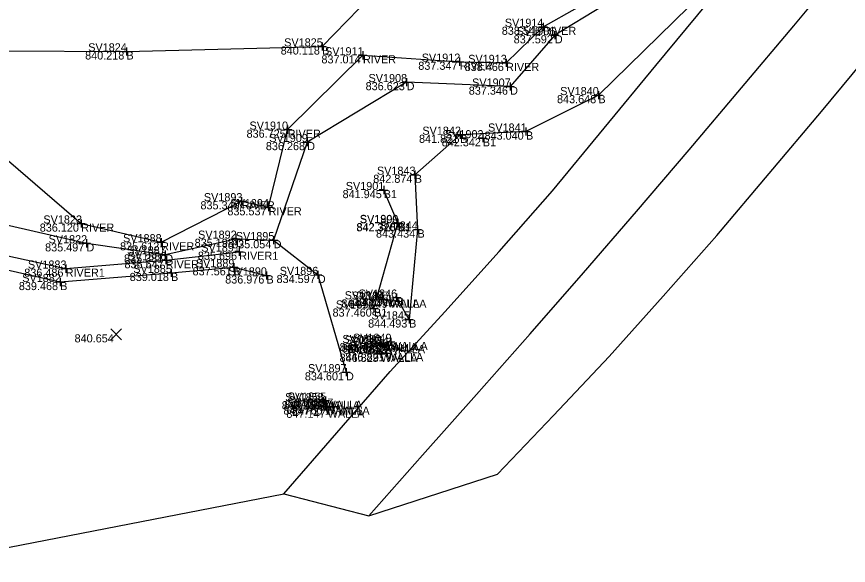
# Model space of a CAD drawing. Extents: x 2125299 to 2129212, y 713100 to 714300.
# Drawn here: x 2127803.8 to 2127906.4, y 713553 to 713620.7 of the extents above; entities that cross this region are included whole.
import ezdxf

# ---------------------------------------------------------------- set-up
doc = ezdxf.new("R2010")
doc.units = 0
for name, color, linetype in [('DR_X_Ditch', 7, 'Continuous'), ('DT_X_Terrain_Boundary', 7, 'Continuous'), ('HY_X_Water_Edge', 7, 'Continuous'), ('PM_X_CL_Double_Solid', 7, 'Continuous'), ('PV_X_EOP', 7, 'Continuous'), ('RW_P_Esmt_TMP', 7, 'Continuous'), ('RW_X_CL_100_Curve_Data', 7, 'Continuous'), ('RW_X_Esmt_CH', 7, 'Continuous'), ('RW_X_Fee_WL', 7, 'Continuous'), ('SV_X_Break_Lines', 7, 'Continuous'), ('SV_X_Mon_Cells_Found', 7, 'Continuous'), ('SV_X_Text_Elevation', 7, 'Continuous')]:
    doc.layers.add(name, color=color, linetype=linetype)

msp = doc.modelspace()

# ---------------------------------------------------------------- linework, layer by layer
at = {"layer": 'DR_X_Ditch'}
for points in [[(2127754.53, 713650.69), (2127755.51, 713649.81), (2127761.02, 713641.8), (2127767.38, 713629.63), (2127773.83, 713613.84), (2127787.1, 713602.06), (2127796.41, 713596.43), (2127812.41, 713592.76), (2127822.14, 713591.39), (2127830.86, 713593.33), (2127835.51, 713593.15), (2127840.96, 713588.86), (2127844.44, 713576.86)], [(2127902.43, 713649.34), (2127886.72, 713632.53), (2127876.19, 713622.06), (2127870.21, 713618.42), (2127864.69, 713612.09), (2127851.92, 713612.64), (2127839.65, 713605.25), (2127835.51, 713593.15)]]:
    msp.add_lwpolyline(points, dxfattribs=at)
at = {"layer": 'DT_X_Terrain_Boundary'}
msp.add_lwpolyline([(2127597.81, 713640.57), (2127738.64, 713599.23), (2127748.23, 713588.26), (2127764.66, 713569.48), (2127770.03, 713566.16), (2127791.25, 713553.04), (2127836.75, 713561.85), (2127847.25, 713559.16), (2127863.15, 713564.3), (2127870.03, 713571.54), (2127876.91, 713578.79), (2127883.56, 713586.26), (2127890.21, 713593.73), (2127896.66, 713601.37), (2127903.1, 713609.02), (2127909.49, 713616.71)], dxfattribs=at)
at = {"layer": 'HY_X_Water_Edge'}
for points in [[(2127760.76, 713650.39), (2127768.15, 713637.25), (2127774.73, 713633.04), (2127778.54, 713623.49), (2127790.38, 713611.58), (2127799.45, 713605.77), (2127811.76, 713595.2), (2127821.63, 713592.89), (2127831.56, 713597.95), (2127834.89, 713597.21), (2127837.24, 713606.78), (2127846.53, 713615.95), (2127858.46, 713615.16), (2127864.19, 713615.01), (2127868.76, 713619.47), (2127877.26, 713624.25)], [(2127759.04, 713637.44), (2127761.13, 713628.45), (2127763.15, 713621.24), (2127764.16, 713612.4), (2127775.86, 713605.03), (2127792.88, 713593.37), (2127809.85, 713589.64), (2127822.2, 713590.68), (2127831.26, 713591.73)]]:
    msp.add_lwpolyline(points, dxfattribs=at)
at = {"layer": 'PM_X_CL_Double_Solid'}
msp.add_lwpolyline([(2127847.25, 713559.16), (2127853.89, 713566.63), (2127860.53, 713574.11), (2127867.15, 713581.61), (2127873.74, 713589.13), (2127880.29, 713596.69), (2127886.77, 713604.3), (2127893.23, 713611.93), (2127899.68, 713619.58), (2127906.08, 713627.26), (2127912.37, 713635.04)], dxfattribs=at)
at = {"layer": 'PV_X_EOP'}
for points in [[(2127836.75, 713561.85), (2127843.31, 713569.4), (2127849.87, 713576.94), (2127856.63, 713584.32), (2127863.34, 713591.74), (2127869.93, 713599.25), (2127876.3, 713606.96), (2127882.68, 713614.67), (2127889.03, 713622.38), (2127895.18, 713630.27), (2127901.47, 713638.05), (2127907.73, 713645.84)], [(2127863.15, 713564.3), (2127870.03, 713571.54), (2127876.91, 713578.79), (2127883.56, 713586.26), (2127890.21, 713593.73), (2127896.66, 713601.37), (2127903.1, 713609.02), (2127909.49, 713616.71)]]:
    msp.add_lwpolyline(points, dxfattribs=at)
at = {"layer": 'SV_X_Break_Lines'}
for points in [[(2127802.01, 713616.51), (2127817.35, 713616.43), (2127841.48, 713617.04), (2127847.58, 713623.34), (2127853.96, 713625.47), (2127861.44, 713624.91), (2127870.57, 713626.11), (2127879.02, 713631.05), (2127890.36, 713639.22), (2127900.49, 713650.27), (2127902.76, 713651.63), (2127904.08, 713651.05), (2127905, 713647.96), (2127904.71, 713645.4), (2127899.81, 713638.31), (2127886.77, 713621.96), (2127875.58, 713611.04), (2127866.65, 713606.54), (2127858.53, 713606.15), (2127852.92, 713601.22), (2127853.26, 713594.46), (2127852.23, 713583.37), (2127850.69, 713586.06)], [(2127735.75, 713636.66), (2127746.04, 713632.28), (2127758.51, 713628.18), (2127762.63, 713621.24), (2127762.07, 713611.19), (2127774.9, 713604.1), (2127791.54, 713592), (2127809.17, 713587.99), (2127822.85, 713589.11), (2127830.59, 713589.8), (2127834.63, 713588.8)], [(2127847.89, 713584.72), (2127850.83, 713595.23), (2127850.85, 713595.27), (2127849.09, 713599.33)]]:
    msp.add_lwpolyline(points, dxfattribs=at)
at = {"layer": 'SV_X_Mon_Cells_Found'}
for p, q in [((2127868.76, 713619.97), (2127868.76, 713618.97)), ((2127868.26, 713619.47), (2127869.26, 713619.47)), ((2127868.76, 713619.47), (2127868.76, 713619.47)), ((2127870.21, 713618.92), (2127870.21, 713617.92)), ((2127869.71, 713618.42), (2127870.71, 713618.42)), ((2127870.21, 713618.42), (2127870.21, 713618.42)), ((2127817.35, 713616.93), (2127817.35, 713615.93)), ((2127840.98, 713617.04), (2127841.98, 713617.04)), ((2127841.48, 713617.54), (2127841.48, 713616.54)), ((2127841.48, 713617.04), (2127841.48, 713617.04)), ((2127816.85, 713616.43), (2127817.85, 713616.43)), ((2127817.35, 713616.43), (2127817.35, 713616.43)), ((2127846.03, 713615.95), (2127847.03, 713615.95)), ((2127846.53, 713616.45), (2127846.53, 713615.45)), ((2127846.53, 713615.95), (2127846.53, 713615.95)), ((2127858.46, 713615.66), (2127858.46, 713614.66)), ((2127857.96, 713615.16), (2127858.96, 713615.16)), ((2127858.46, 713615.16), (2127858.46, 713615.16)), ((2127863.69, 713615.01), (2127864.69, 713615.01)), ((2127864.19, 713615.51), (2127864.19, 713614.51)), ((2127864.19, 713615.01), (2127864.19, 713615.01)), ((2127851.42, 713612.64), (2127852.42, 713612.64)), ((2127851.92, 713613.14), (2127851.92, 713612.14)), ((2127851.92, 713612.64), (2127851.92, 713612.64)), ((2127864.69, 713612.59), (2127864.69, 713611.59)), ((2127864.19, 713612.09), (2127865.19, 713612.09)), ((2127864.69, 713612.09), (2127864.69, 713612.09)), ((2127875.58, 713611.54), (2127875.58, 713610.54)), ((2127875.08, 713611.04), (2127876.08, 713611.04)), ((2127875.58, 713611.04), (2127875.58, 713611.04)), ((2127836.74, 713606.78), (2127837.74, 713606.78)), ((2127837.24, 713607.28), (2127837.24, 713606.28)), ((2127837.24, 713606.78), (2127837.24, 713606.78)), ((2127858.53, 713606.65), (2127858.53, 713605.65)), ((2127866.15, 713606.54), (2127867.15, 713606.54)), ((2127866.65, 713607.04), (2127866.65, 713606.04)), ((2127866.65, 713606.54), (2127866.65, 713606.54)), ((2127839.65, 713605.75), (2127839.65, 713604.75)), ((2127858.03, 713606.15), (2127859.03, 713606.15)), ((2127858.53, 713606.15), (2127858.53, 713606.15)), ((2127860.82, 713605.72), (2127861.82, 713605.72)), ((2127861.32, 713606.22), (2127861.32, 713605.22)), ((2127861.32, 713605.72), (2127861.32, 713605.72)), ((2127839.15, 713605.25), (2127840.15, 713605.25)), ((2127839.65, 713605.25), (2127839.65, 713605.25)), ((2127852.92, 713601.72), (2127852.92, 713600.72)), ((2127852.42, 713601.22), (2127853.42, 713601.22)), ((2127852.92, 713601.22), (2127852.92, 713601.22)), ((2127848.59, 713599.33), (2127849.59, 713599.33)), ((2127849.09, 713599.83), (2127849.09, 713598.83)), ((2127849.09, 713599.33), (2127849.09, 713599.33)), ((2127831.56, 713598.45), (2127831.56, 713597.45)), ((2127831.06, 713597.95), (2127832.06, 713597.95)), ((2127831.56, 713597.95), (2127831.56, 713597.95)), ((2127834.39, 713597.21), (2127835.39, 713597.21)), ((2127834.89, 713597.71), (2127834.89, 713596.71)), ((2127834.89, 713597.21), (2127834.89, 713597.21)), ((2127811.26, 713595.2), (2127812.26, 713595.2)), ((2127811.76, 713595.7), (2127811.76, 713594.7)), ((2127811.76, 713595.2), (2127811.76, 713595.2)), ((2127850.33, 713595.23), (2127851.33, 713595.23)), ((2127850.35, 713595.27), (2127851.35, 713595.27)), ((2127850.83, 713595.73), (2127850.83, 713594.73)), ((2127850.83, 713595.23), (2127850.83, 713595.23)), ((2127850.85, 713595.77), (2127850.85, 713594.77)), ((2127850.85, 713595.27), (2127850.85, 713595.27)), ((2127852.76, 713594.46), (2127853.76, 713594.46)), ((2127853.26, 713594.96), (2127853.26, 713593.96)), ((2127853.26, 713594.46), (2127853.26, 713594.46)), ((2127812.41, 713593.26), (2127812.41, 713592.26)), ((2127821.63, 713593.39), (2127821.63, 713592.39)), ((2127830.36, 713593.33), (2127831.36, 713593.33)), ((2127830.86, 713593.83), (2127830.86, 713592.83)), ((2127830.86, 713593.33), (2127830.86, 713593.33)), ((2127835.01, 713593.15), (2127836.01, 713593.15)), ((2127835.51, 713593.65), (2127835.51, 713592.65)), ((2127835.51, 713593.15), (2127835.51, 713593.15)), ((2127811.91, 713592.76), (2127812.91, 713592.76)), ((2127812.41, 713592.76), (2127812.41, 713592.76)), ((2127821.13, 713592.89), (2127822.13, 713592.89)), ((2127821.63, 713592.89), (2127821.63, 713592.89)), ((2127831.26, 713592.23), (2127831.26, 713591.23)), ((2127821.64, 713591.39), (2127822.64, 713591.39)), ((2127822.14, 713591.89), (2127822.14, 713590.89)), ((2127822.14, 713591.39), (2127822.14, 713591.39)), ((2127822.2, 713591.18), (2127822.2, 713590.18)), ((2127830.76, 713591.73), (2127831.76, 713591.73)), ((2127831.26, 713591.73), (2127831.26, 713591.73)), ((2127809.85, 713590.14), (2127809.85, 713589.14)), ((2127821.7, 713590.68), (2127822.7, 713590.68)), ((2127822.2, 713590.68), (2127822.2, 713590.68)), ((2127830.59, 713590.3), (2127830.59, 713589.3)), ((2127809.35, 713589.64), (2127810.35, 713589.64)), ((2127809.85, 713589.64), (2127809.85, 713589.64)), ((2127822.35, 713589.11), (2127823.35, 713589.11)), ((2127822.85, 713589.61), (2127822.85, 713588.61)), ((2127822.85, 713589.11), (2127822.85, 713589.11)), ((2127830.09, 713589.8), (2127831.09, 713589.8)), ((2127830.59, 713589.8), (2127830.59, 713589.8)), ((2127834.63, 713589.3), (2127834.63, 713588.3)), ((2127840.96, 713589.36), (2127840.96, 713588.36)), ((2127808.67, 713587.99), (2127809.67, 713587.99)), ((2127809.17, 713588.49), (2127809.17, 713587.49)), ((2127809.17, 713587.99), (2127809.17, 713587.99)), ((2127834.13, 713588.8), (2127835.13, 713588.8)), ((2127834.63, 713588.8), (2127834.63, 713588.8)), ((2127840.46, 713588.86), (2127841.46, 713588.86)), ((2127840.96, 713588.86), (2127840.96, 713588.86)), ((2127848.48, 713585.85), (2127849.48, 713585.85)), ((2127848.98, 713586.35), (2127848.98, 713585.35)), ((2127848.98, 713585.85), (2127848.98, 713585.85)), ((2127849.83, 713586.31), (2127849.83, 713585.31)), ((2127850.19, 713586.06), (2127851.19, 713586.06)), ((2127850.69, 713586.56), (2127850.69, 713585.56)), ((2127850.69, 713586.06), (2127850.69, 713586.06)), ((2127847.89, 713585.22), (2127847.89, 713584.22)), ((2127849.33, 713585.81), (2127850.33, 713585.81)), ((2127849.83, 713585.81), (2127849.83, 713585.81)), ((2127847.39, 713584.72), (2127848.39, 713584.72)), ((2127847.89, 713584.72), (2127847.89, 713584.72)), ((2127852.23, 713583.87), (2127852.23, 713582.87)), ((2127851.73, 713583.37), (2127852.73, 713583.37)), ((2127852.23, 713583.37), (2127852.23, 713583.37)), ((2127848.72, 713580.96), (2127848.72, 713579.96)), ((2127848.97, 713580.84), (2127848.97, 713579.84)), ((2127849.66, 713580.71), (2127849.66, 713579.71)), ((2127849.98, 713581.11), (2127849.98, 713580.11)), ((2127848.22, 713580.46), (2127849.22, 713580.46)), ((2127848.47, 713580.34), (2127849.47, 713580.34)), ((2127848.72, 713580.46), (2127848.72, 713580.46)), ((2127848.97, 713580.34), (2127848.97, 713580.34)), ((2127849.16, 713580.21), (2127850.16, 713580.21)), ((2127849.44, 713579.72), (2127849.44, 713578.72)), ((2127849.48, 713580.61), (2127850.48, 713580.61)), ((2127849.66, 713580.21), (2127849.66, 713580.21)), ((2127849.98, 713580.61), (2127849.98, 713580.61)), ((2127848.24, 713579.14), (2127849.24, 713579.14)), ((2127848.74, 713579.64), (2127848.74, 713578.64)), ((2127848.74, 713579.14), (2127848.74, 713579.14)), ((2127848.94, 713579.22), (2127849.94, 713579.22)), ((2127849.44, 713579.22), (2127849.44, 713579.22)), ((2127843.94, 713576.86), (2127844.94, 713576.86)), ((2127844.44, 713577.36), (2127844.44, 713576.36)), ((2127844.44, 713576.86), (2127844.44, 713576.86)), ((2127841.63, 713573.79), (2127841.63, 713572.79)), ((2127841.91, 713573.86), (2127841.91, 713572.86)), ((2127841.13, 713573.29), (2127842.13, 713573.29)), ((2127841.33, 713572.65), (2127842.33, 713572.65)), ((2127841.41, 713573.36), (2127842.41, 713573.36)), ((2127841.63, 713573.29), (2127841.63, 713573.29)), ((2127841.83, 713573.15), (2127841.83, 713572.15)), ((2127841.83, 713572.65), (2127841.83, 713572.65)), ((2127841.91, 713573.36), (2127841.91, 713573.36)), ((2127842.18, 713572.74), (2127842.18, 713571.74)), ((2127842.32, 713572.62), (2127843.32, 713572.62)), ((2127842.82, 713573.12), (2127842.82, 713572.12)), ((2127842.82, 713572.62), (2127842.82, 713572.62)), ((2127841.68, 713572.24), (2127842.68, 713572.24)), ((2127842.18, 713572.24), (2127842.18, 713572.24))]:
    msp.add_line(p, q, dxfattribs=at)
at = {"layer": 'SV_X_Text_Elevation'}
for p, q in [((2127815.41, 713580.87), (2127816.74, 713582.21)), ((2127815.41, 713582.21), (2127816.74, 713580.87))]:
    msp.add_line(p, q, dxfattribs=at)

# ---------------------------------------------------------------- texts
at = {"layer": 'RW_P_Esmt_TMP'}
for s, p in [('RIVER', (2127868.76, 713618.47)), ('D', (2127870.21, 713617.42)), ('B', (2127841.48, 713616.04)), ('B', (2127817.35, 713615.43)), ('RIVER', (2127846.53, 713614.95)), ('RIVER', (2127858.46, 713614.16)), ('RIVER', (2127864.19, 713614.01)), ('D', (2127851.92, 713611.64)), ('D', (2127864.69, 713611.09)), ('B', (2127875.58, 713610.04)), ('RIVER', (2127837.24, 713605.78)), ('B', (2127866.65, 713605.54)), ('B', (2127858.53, 713605.15)), ('B1', (2127861.32, 713604.72)), ('D', (2127839.65, 713604.25)), ('B', (2127852.92, 713600.22)), ('B1', (2127849.09, 713598.33)), ('RIVER', (2127831.56, 713596.95)), ('RIVER', (2127834.89, 713596.21)), ('RIVER', (2127811.76, 713594.2)), ('B1', (2127850.83, 713594.23)), ('B1', (2127850.85, 713594.27)), ('B', (2127853.26, 713593.46)), ('D', (2127830.86, 713592.33)), ('D', (2127835.51, 713592.15)), ('D', (2127812.41, 713591.76)), ('RIVER', (2127821.63, 713591.89)), ('D', (2127822.14, 713590.39)), ('RIVER1', (2127831.26, 713590.73)), ('RIVER1', (2127822.2, 713589.68)), ('RIVER1', (2127809.85, 713588.64)), ('B', (2127822.85, 713588.11)), ('B', (2127830.59, 713588.81)), ('B', (2127809.17, 713586.99)), ('B', (2127834.63, 713587.8)), ('D', (2127840.96, 713587.86)), ('B', (2127850.69, 713585.06)), ('B1', (2127847.89, 713583.72)), ('B', (2127852.23, 713582.37)), ('D', (2127844.44, 713575.86))]:
    msp.add_text(s, height=1, dxfattribs=at).set_placement(p)
at = {"layer": 'RW_X_CL_100_Curve_Data'}
for s, p in [('SV1848', (2127844.28, 713585.85)), ('844.770', (2127843.87, 713584.85)), ('SV1847', (2127845.14, 713585.81)), ('WALLA', (2127848.98, 713584.85)), ('844.749', (2127844.75, 713584.81)), ('WALLA', (2127849.83, 713584.81)), ('SV1850', (2127844, 713580.46)), ('SV1851', (2127844.29, 713580.34)), ('SV1854', (2127844.94, 713580.21)), ('SV1849', (2127845.3, 713580.61)), ('844.785', (2127843.65, 713579.46)), ('846.823', (2127843.91, 713579.34)), ('SV1852', (2127844.07, 713579.14)), ('846.812', (2127844.59, 713579.21)), ('SV1853', (2127844.78, 713579.22)), ('844.852', (2127844.91, 713579.61)), ('WALLA', (2127848.72, 713579.46)), ('WALLA', (2127848.97, 713579.34)), ('WALLA', (2127849.66, 713579.21)), ('WALLA', (2127849.98, 713579.61)), ('846.829', (2127843.65, 713578.14)), ('846.821', (2127844.36, 713578.22)), ('WALLA', (2127848.74, 713578.14)), ('WALLA', (2127849.44, 713578.22)), ('SV1858', (2127836.93, 713573.29)), ('SV1859', (2127837.14, 713572.65)), ('SV1855', (2127837.24, 713573.36)), ('SV1857', (2127838.12, 713572.62)), ('845.250', (2127836.51, 713572.29)), ('845.760', (2127836.71, 713571.65)), ('847.158', (2127836.81, 713572.36)), ('SV1856', (2127837.47, 713572.24)), ('847.171', (2127837.73, 713571.62)), ('WALLA', (2127841.63, 713572.29)), ('WALLA', (2127841.83, 713571.65)), ('WALLA', (2127841.91, 713572.36)), ('WALLA', (2127842.82, 713571.62)), ('847.147', (2127837.08, 713571.24)), ('WALLA', (2127842.18, 713571.24))]:
    msp.add_text(s, height=1, dxfattribs=at).set_placement(p)
at = {"layer": 'RW_X_Esmt_CH'}
for s, p in [('SV1914', (2127864.04, 713619.47)), ('SV1906', (2127865.5, 713618.42)), ('SV1825', (2127836.81, 713617.04)), ('SV1824', (2127812.63, 713616.43)), ('SV1911', (2127841.85, 713615.95)), ('SV1912', (2127853.78, 713615.16)), ('SV1913', (2127859.52, 713615.01)), ('SV1908', (2127847.22, 713612.64)), ('SV1907', (2127860, 713612.09)), ('SV1840', (2127870.87, 713611.04)), ('SV1910', (2127832.53, 713606.78)), ('SV1841', (2127861.97, 713606.54)), ('SV1842', (2127853.86, 713606.15)), ('SV1902', (2127856.65, 713605.72)), ('SV1909', (2127834.97, 713605.25)), ('SV1843', (2127848.26, 713601.22)), ('SV1901', (2127844.41, 713599.33)), ('SV1893', (2127826.9, 713597.95)), ('SV1894', (2127830.17, 713597.21)), ('SV1823', (2127807.1, 713595.2)), ('SV1900', (2127846.14, 713595.27)), ('SV1899', (2127846.15, 713595.23)), ('SV1844', (2127848.54, 713594.46)), ('SV1892', (2127826.19, 713593.33)), ('SV1895', (2127830.84, 713593.15)), ('SV1822', (2127807.74, 713592.76)), ('SV1888', (2127816.93, 713592.89)), ('SV1887', (2127817.44, 713591.39)), ('SV1891', (2127826.58, 713591.73)), ('SV1886', (2127817.5, 713590.68)), ('SV1883', (2127805.19, 713589.64)), ('SV1885', (2127818.19, 713589.11)), ('SV1889', (2127825.91, 713589.8)), ('SV1882', (2127804.49, 713587.99)), ('SV1890', (2127829.92, 713588.8)), ('SV1896', (2127836.26, 713588.86)), ('SV1846', (2127845.99, 713586.06)), ('SV1898', (2127843.19, 713584.72)), ('SV1845', (2127847.57, 713583.37)), ('SV1897', (2127839.75, 713576.86))]:
    msp.add_text(s, height=1, dxfattribs=at).set_placement(p)
at = {"layer": 'RW_X_Fee_WL'}
for s, p in [('838.546', (2127863.66, 713618.47)), ('837.592', (2127865.13, 713617.42)), ('840.118', (2127836.38, 713616.04)), ('840.218', (2127812.25, 713615.43)), ('837.014', (2127841.41, 713614.95)), ('837.347', (2127853.36, 713614.16)), ('838.466', (2127859.08, 713614.01)), ('836.623', (2127846.86, 713611.64)), ('837.346', (2127859.59, 713611.09)), ('843.648', (2127870.48, 713610.04)), ('836.725', (2127832.17, 713605.78)), ('843.040', (2127861.53, 713605.54)), ('841.821', (2127853.45, 713605.15)), ('842.342', (2127856.25, 713604.72)), ('836.268', (2127834.55, 713604.25)), ('842.874', (2127847.8, 713600.22)), ('841.945', (2127844.02, 713598.33)), ('835.349', (2127826.48, 713596.95)), ('835.537', (2127829.8, 713596.21)), ('836.120', (2127806.65, 713594.2)), ('842.320', (2127845.72, 713594.23)), ('842.318', (2127845.75, 713594.27)), ('843.434', (2127848.14, 713593.46)), ('835.198', (2127825.76, 713592.33)), ('835.054', (2127830.39, 713592.15)), ('835.497', (2127807.31, 713591.76)), ('835.612', (2127816.56, 713591.89)), ('835.381', (2127817.05, 713590.39)), ('835.696', (2127826.16, 713590.73)), ('835.647', (2127817.11, 713589.68)), ('836.486', (2127804.74, 713588.64)), ('839.018', (2127817.75, 713588.11)), ('837.561', (2127825.51, 713588.81)), ('839.468', (2127804.07, 713586.99)), ('836.976', (2127829.53, 713587.8)), ('834.597', (2127835.87, 713587.86)), ('842.922', (2127845.62, 713585.06)), ('837.460', (2127842.78, 713583.72)), ('844.493', (2127847.17, 713582.37)), ('840.654', (2127810.95, 713580.54)), ('834.601', (2127839.36, 713575.86))]:
    msp.add_text(s, height=1, dxfattribs=at).set_placement(p)

doc.saveas('drawing.dxf')
